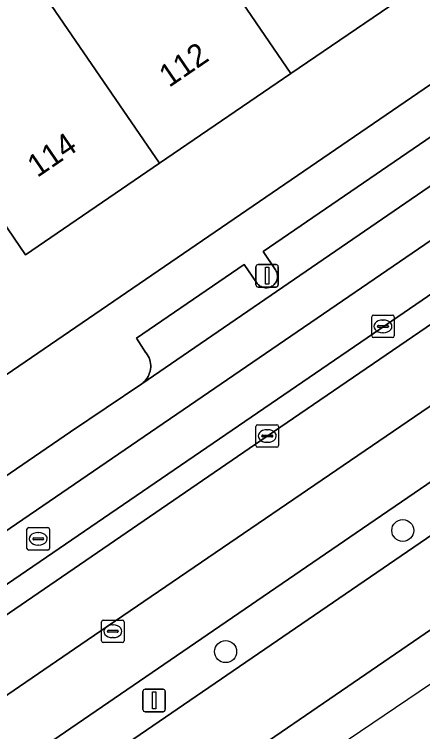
# Model space of a CAD drawing. Extents: x 157445 to 158888, y 383061 to 384688.
# Drawn here: x 158237.61 to 158255.74, y 383403.58 to 383435.44 of the extents above; entities that cross this region are included whole.
import ezdxf

# ---------------------------------------------------------------- set-up
doc = ezdxf.new("R2010")
doc.units = 0
for name, color, linetype in [('IMGEO_Berm_groen', 7, 'Continuous'), ('IMGEO_Boom', 7, 'Continuous'), ('IMGEO_Erf', 7, 'Continuous'), ('IMGEO_Fietspad_gesloten', 7, 'Continuous'), ('IMGEO_Groenvoorziening', 7, 'Continuous'), ('IMGEO_Haag', 7, 'Continuous'), ('IMGEO_Kolk', 7, 'Continuous'), ('IMGEO_Lichtmast', 7, 'Continuous'), ('IMGEO_OVBaan_gesloten', 7, 'Continuous'), ('IMGEO_Pand', 7, 'Continuous'), ('IMGEO_Pand_nummerreeks', 7, 'Continuous'), ('IMGEO_Parkeervlak_open', 7, 'Continuous'), ('IMGEO_Rijbaan_lokaal_open', 7, 'Continuous'), ('IMGEO_Rijbaan_regionaal_gesloten', 7, 'Continuous'), ('IMGEO_Rioolput', 7, 'Continuous'), ('IMGEO_Voetpad_open', 7, 'Continuous')]:
    doc.layers.add(name, color=color, linetype=linetype)

msp = doc.modelspace()

# ---------------------------------------------------------------- linework, layer by layer
at = {"layer": 'IMGEO_Berm_groen'}
msp.add_lwpolyline([(158221.925, 383388.892), (158288.761, 383434.651), (158292.434, 383437.186), (158297.742, 383440.818), (158298.869, 383441.589), (158297.72, 383443.271), (158292.199, 383439.39), (158253.351, 383412.794), (158220.288, 383390.177), (158147.587, 383340.38), (158131.044, 383329.063), (158130.63, 383328.78), (158121.696, 383323.264), (158114.538, 383319.21), (158116.355, 383316.875), (158118.236, 383318.161), (158122.571, 383321.116), (158122.69, 383320.962), (158147.648, 383338.001)], close=True, dxfattribs=at)
at = {"layer": 'IMGEO_Boom'}
for centre in [(158254.856, 383412.515), (158246.986, 383407.135)]:
    msp.add_circle(centre, 0.489, dxfattribs=at)
at = {"layer": 'IMGEO_Erf'}
for points in [[(158261.53, 383440.776), (158255.722, 383436.805), (158249.888, 383432.816), (158244.054, 383428.827), (158238.106, 383424.761), (158235.228, 383428.972), (158233.281, 383427.642), (158233.14, 383427.545), (158234.427, 383425.663), (158228.484, 383421.6), (158224.793, 383426.999), (158230.737, 383431.063), (158231.048, 383430.609), (158231.188, 383430.705), (158233.137, 383432.038), (158231.98, 383433.73), (158237.925, 383437.797), (158243.757, 383441.787), (158249.591, 383445.778), (158255.366, 383449.729), (158256.523, 383448.037)], [(158223.297, 383422.668), (158227.333, 383416.806), (158227.586, 383416.813), (158227.93, 383416.511), (158228.071, 383416.31), (158228.229, 383416.122), (158228.404, 383415.949), (158228.593, 383415.793), (158228.795, 383415.654), (158229.009, 383415.533), (158229.233, 383415.432), (158229.465, 383415.352), (158229.703, 383415.292), (158229.946, 383415.255), (158230.191, 383415.239), (158230.437, 383415.244), (158230.68, 383415.272), (158230.921, 383415.322), (158231.156, 383415.393), (158231.384, 383415.484), (158231.603, 383415.596), (158231.811, 383415.726), (158231.883, 383415.778), (158272.122, 383443.31)]]:
    msp.add_lwpolyline(points, dxfattribs=at)
at = {"layer": 'IMGEO_Fietspad_gesloten'}
for points in [[(158187.266, 383378.304), (158283.613, 383444.253), (158285.485, 383445.421)], [(158264.364, 383433.502), (158243.266, 383419.033), (158240.107, 383416.893), (158231.018, 383410.676), (158222.662, 383405.033), (158216.122, 383400.492), (158211.209, 383397.104), (158189.236, 383382.055), (158186.221, 383380.023), (158186.115, 383379.952), (158185.306, 383379.446), (158177.375, 383375.018), (158176.619, 383374.65), (158176.474, 383374.585), (158172.535, 383372.428), (158169.599, 383370.501), (158169.322, 383370.3), (158168.758, 383369.891), (158163.249, 383365.637), (158161.075, 383363.872), (158159.242, 383362.325), (158158.671, 383361.835)]]:
    msp.add_lwpolyline(points, dxfattribs=at)
at = {"layer": 'IMGEO_Groenvoorziening'}
for points in [[(158248.84, 383416.701), (158278.53, 383437.014), (158282.685, 383439.867), (158290.446, 383445.197), (158291.741, 383446.132), (158293.116, 383447.183)], [(158267.42, 383430.778), (158253.835, 383421.451), (158233.587, 383407.607), (158220.735, 383398.828), (158218.073, 383397), (158207.964, 383390.082), (158175.757, 383368.034), (158174.147, 383366.948), (158170.828, 383364.667), (158169.555, 383363.8), (158154.269, 383353.34), (158144.169, 383346.438), (158136.533, 383341.212)], [(158097.631, 383314.81), (158104.807, 383319.769), (158115.926, 383327.372), (158122.206, 383331.037), (158124.828, 383332.496), (158130.229, 383335.664), (158132.829, 383337.348), (158135.426, 383339.03), (158135.445, 383339.043), (158145.556, 383345.975), (158161.638, 383357.025), (158178.512, 383368.554), (158196.488, 383380.88), (158218.524, 383395.939), (158231.113, 383404.563), (158248.84, 383416.701)]]:
    msp.add_lwpolyline(points, dxfattribs=at)
at = {"layer": 'IMGEO_Haag'}
for points in [[(158097.631, 383314.81), (158104.807, 383319.769), (158115.926, 383327.372), (158122.206, 383331.037), (158124.828, 383332.496), (158130.229, 383335.664), (158132.829, 383337.348), (158135.426, 383339.03), (158135.445, 383339.043), (158145.556, 383345.975), (158161.638, 383357.025), (158178.512, 383368.554), (158196.488, 383380.88), (158218.524, 383395.939), (158231.113, 383404.563), (158248.84, 383416.701), (158278.53, 383437.014)], [(158267.42, 383430.778), (158253.835, 383421.451), (158233.587, 383407.607), (158220.735, 383398.828), (158218.073, 383397), (158207.964, 383390.082), (158175.757, 383368.034), (158174.147, 383366.948), (158170.828, 383364.667), (158169.555, 383363.8), (158154.269, 383353.34), (158144.169, 383346.438), (158136.533, 383341.212)]]:
    msp.add_lwpolyline(points, dxfattribs=at)
at = {"layer": 'IMGEO_Kolk'}
for p, q in [((158253.474, 383421.155), (158253.474, 383422.007)), ((158253.549, 383422.081), (158254.401, 383422.081)), ((158253.962, 383421.861), (158253.987, 383421.861)), ((158254.475, 383422.007), (158254.475, 383421.155)), ((158253.733, 383421.575), (158253.733, 383421.587)), ((158254.171, 383421.538), (158253.773, 383421.538)), ((158253.776, 383421.624), (158254.174, 383421.624)), ((158254.217, 383421.587), (158254.217, 383421.575)), ((158253.985, 383421.301), (158253.96, 383421.301)), ((158254.401, 383421.081), (158253.549, 383421.081)), ((158248.336, 383416.285), (158248.336, 383417.137)), ((158248.411, 383417.211), (158249.263, 383417.211)), ((158249.337, 383417.137), (158249.337, 383416.285)), ((158248.638, 383416.754), (158249.036, 383416.754)), ((158248.824, 383416.991), (158248.849, 383416.991)), ((158248.595, 383416.705), (158248.595, 383416.717)), ((158249.033, 383416.668), (158248.635, 383416.668)), ((158249.079, 383416.717), (158249.079, 383416.705)), ((158249.263, 383416.211), (158248.411, 383416.211)), ((158248.847, 383416.431), (158248.822, 383416.431))]:
    msp.add_line(p, q, dxfattribs=at)
for points in [[(158253.474, 383421.155), (158253.474, 383422.007)], [(158253.549, 383422.081), (158254.401, 383422.081)], [(158254.475, 383422.007), (158254.475, 383421.155)], [(158254.401, 383421.081), (158253.549, 383421.081)], [(158248.336, 383416.285), (158248.336, 383417.137)], [(158248.411, 383417.211), (158249.263, 383417.211)], [(158249.337, 383417.137), (158249.337, 383416.285)], [(158249.263, 383416.211), (158248.411, 383416.211)]]:
    msp.add_lwpolyline(points, dxfattribs=at)
for centre, radius, start, end in [((158253.551, 383422.005), 0.0765, 91.552, 178.448), ((158253.551, 383422.005), 0.0765, 91.552, 178.448), ((158254.399, 383422.005), 0.0765, 1.552, 88.448), ((158254.399, 383422.005), 0.0765, 1.552, 88.448), ((158253.773, 383421.584), 0.0403, 85.8775, 175.7526), ((158253.77, 383421.574), 0.0366, 178.938, 274.7102), ((158254.174, 383421.581), 0.043, 264.8664, 352.4533), ((158254.178, 383421.586), 0.0386, 1.7309, 96.639), ((158253.551, 383421.157), 0.0765, 181.552, 268.448), ((158253.551, 383421.157), 0.0765, 181.552, 268.448), ((158254.399, 383421.157), 0.0765, 271.552, 358.448), ((158254.399, 383421.157), 0.0765, 271.552, 358.448), ((158248.413, 383417.135), 0.0765, 91.552, 178.448), ((158248.413, 383417.135), 0.0765, 91.552, 178.448), ((158249.261, 383417.135), 0.0765, 1.552, 88.448), ((158249.261, 383417.135), 0.0765, 1.552, 88.448), ((158248.635, 383416.714), 0.0403, 85.8775, 175.7526), ((158249.04, 383416.716), 0.0386, 1.7309, 96.639), ((158248.632, 383416.704), 0.0366, 178.938, 274.7102), ((158249.036, 383416.711), 0.043, 264.8664, 352.4533), ((158248.413, 383416.287), 0.0765, 181.552, 268.448), ((158248.413, 383416.287), 0.0765, 181.552, 268.448), ((158249.261, 383416.287), 0.0765, 271.552, 358.448), ((158249.261, 383416.287), 0.0765, 271.552, 358.448)]:
    msp.add_arc(centre, radius, start, end, dxfattribs=at)
for centre, major_axis, ratio, start_param, end_param in [((158253.961, 383421.581), (-0.387, 0.002), 0.722429, 4.712389, 7.853982), ((158253.986, 383421.581), (-0.39, 0.002), 0.717154, 1.570796, 4.712389), ((158248.823, 383416.711), (-0.387, 0.002), 0.722429, 4.712389, 7.853982), ((158248.848, 383416.711), (-0.39, 0.002), 0.717154, 1.570796, 4.712389)]:
    msp.add_ellipse(centre, major_axis=major_axis, ratio=ratio, start_param=start_param, end_param=end_param, dxfattribs=at)
at = {"layer": 'IMGEO_Lichtmast'}
for p, q in [((158248.337, 383423.43), (158248.337, 383424.23)), ((158248.337, 383424.23), (158248.337, 383423.43)), ((158248.437, 383424.33), (158249.227, 383424.33)), ((158249.227, 383424.33), (158248.437, 383424.33)), ((158249.327, 383424.23), (158249.327, 383423.43)), ((158249.327, 383423.43), (158249.327, 383424.23)), ((158249.227, 383423.33), (158248.437, 383423.33)), ((158248.437, 383423.33), (158249.227, 383423.33)), ((158243.318, 383404.566), (158243.318, 383405.366)), ((158243.318, 383405.366), (158243.318, 383404.566)), ((158243.418, 383405.466), (158244.208, 383405.466)), ((158244.208, 383405.466), (158243.418, 383405.466)), ((158244.308, 383405.366), (158244.308, 383404.566)), ((158244.308, 383404.566), (158244.308, 383405.366)), ((158244.208, 383404.466), (158243.418, 383404.466)), ((158243.418, 383404.466), (158244.208, 383404.466))]:
    msp.add_line(p, q, dxfattribs=at)
for points in [[(158248.757, 383424.205), (158248.907, 383424.205), (158248.907, 383423.455), (158248.757, 383423.455), (158248.757, 383424.205)], [(158243.738, 383405.341), (158243.888, 383405.341), (158243.888, 383404.591), (158243.738, 383404.591), (158243.738, 383405.341)]]:
    msp.add_lwpolyline(points, dxfattribs=at)
for centre, start, end in [((158248.437, 383424.23), 90, 180), ((158248.437, 383424.23), 90, 180), ((158249.227, 383424.23), 0, 90), ((158249.227, 383424.23), 360, 90), ((158248.437, 383423.43), 180, 270), ((158248.437, 383423.43), 180, 270), ((158249.227, 383423.43), 270, 0), ((158249.227, 383423.43), 270, 0), ((158243.418, 383405.366), 90, 180), ((158243.418, 383405.366), 90, 180), ((158244.208, 383405.366), 0, 90), ((158244.208, 383405.366), 360, 90), ((158243.418, 383404.566), 180, 270), ((158243.418, 383404.566), 180, 270), ((158244.208, 383404.566), 270, 0), ((158244.208, 383404.566), 270, 0)]:
    msp.add_arc(centre, 0.1, start, end, dxfattribs=at)
at = {"layer": 'IMGEO_OVBaan_gesloten'}
msp.add_lwpolyline([(158105.383, 383303.781), (158135.353, 383324.049), (158142.057, 383328.583), (158290.829, 383429.195), (158320.176, 383449.816), (158338.196, 383462.478), (158337.159, 383463.965), (158306.253, 383442.35), (158269.724, 383417.452), (158230.256, 383390.412), (158196.708, 383367.445), (158164.294, 383345.275), (158134.65, 383324.869), (158121.592, 383315.968), (158104.891, 383304.477)], close=True, dxfattribs=at)
msp.add_lwpolyline([(158288.761, 383434.651), (158221.925, 383388.892), (158147.648, 383338.001), (158122.69, 383320.962), (158122.571, 383321.116), (158118.236, 383318.161), (158116.355, 383316.875), (158107.899, 383311.095), (158102.711, 383307.543), (158104.822, 383304.574), (158104.891, 383304.477), (158121.592, 383315.968), (158134.65, 383324.869), (158164.294, 383345.275), (158196.708, 383367.445), (158230.256, 383390.412), (158269.724, 383417.452)], dxfattribs=at)
at = {"layer": 'IMGEO_Pand'}
for points in [[(158249.888, 383432.816), (158255.722, 383436.805), (158249.703, 383445.615), (158249.591, 383445.778), (158243.757, 383441.787), (158243.86, 383441.637)], [(158237.925, 383437.797), (158238.019, 383437.659), (158244.054, 383428.827), (158249.888, 383432.816), (158243.86, 383441.637), (158243.757, 383441.787)], [(158233.281, 383427.642), (158235.228, 383428.972), (158238.106, 383424.761), (158244.054, 383428.827), (158238.019, 383437.659), (158237.925, 383437.797), (158231.98, 383433.73), (158233.137, 383432.038), (158231.188, 383430.705)]]:
    msp.add_lwpolyline(points, close=True, dxfattribs=at)
at = {"layer": 'IMGEO_Parkeervlak_open'}
msp.add_lwpolyline([(158262.546, 383434.413), (158248.649, 383424.903), (158249.197, 383424.096), (158249.214, 383424.07), (158249.237, 383424.031), (158249.255, 383423.99), (158249.271, 383423.948), (158249.282, 383423.904), (158249.289, 383423.86), (158249.292, 383423.815), (158249.291, 383423.77), (158249.287, 383423.725), (158249.278, 383423.68), (158249.265, 383423.637), (158249.248, 383423.595), (158249.228, 383423.555), (158249.205, 383423.517), (158249.177, 383423.481), (158249.147, 383423.447), (158249.114, 383423.416), (158249.079, 383423.389), (158249.041, 383423.365), (158249.001, 383423.344), (158248.959, 383423.327), (158248.916, 383423.313), (158248.872, 383423.304), (158248.827, 383423.298), (158248.782, 383423.297), (158248.737, 383423.299), (158248.692, 383423.306), (158248.649, 383423.317), (158248.606, 383423.331), (158248.565, 383423.349), (158248.525, 383423.371), (158248.488, 383423.396), (158248.453, 383423.425), (158248.421, 383423.456), (158248.391, 383423.49), (158248.365, 383423.527), (158247.809, 383424.329), (158243.024, 383421.058), (158243.448, 383420.412), (158243.455, 383420.403), (158243.505, 383420.333), (158243.549, 383420.259), (158243.586, 383420.182), (158243.616, 383420.101), (158243.638, 383420.019), (158243.653, 383419.934), (158243.66, 383419.849), (158243.66, 383419.763), (158243.652, 383419.678), (158243.637, 383419.593), (158243.614, 383419.511), (158243.583, 383419.43), (158243.546, 383419.353), (158243.502, 383419.28), (158243.452, 383419.21), (158243.395, 383419.146), (158243.333, 383419.086), (158243.266, 383419.033), (158264.364, 383433.502)], dxfattribs=at)
at = {"layer": 'IMGEO_Rijbaan_lokaal_open'}
for points in [[(158283.613, 383444.253), (158187.266, 383378.304)], [(158233.587, 383407.607), (158253.835, 383421.451), (158267.42, 383430.778), (158279.382, 383438.959), (158282.059, 383440.783)]]:
    msp.add_lwpolyline(points, dxfattribs=at)
at = {"layer": 'IMGEO_Rijbaan_regionaal_gesloten'}
for points in [[(158147.587, 383340.38), (158220.288, 383390.177), (158253.351, 383412.794), (158292.199, 383439.39)], [(158278.53, 383437.014), (158248.84, 383416.701), (158231.113, 383404.563), (158218.524, 383395.939), (158196.488, 383380.88), (158178.512, 383368.554), (158161.638, 383357.025), (158145.556, 383345.975), (158135.445, 383339.043)], [(158138.48, 383337.556), (158158.157, 383351.03), (158164.879, 383355.633), (158168.626, 383358.198), (158174.157, 383361.985), (158187.898, 383371.394), (158211.135, 383387.305), (158217.716, 383391.811), (158240.844, 383407.647), (158257.282, 383418.872)], [(158257.282, 383418.872), (158240.844, 383407.647), (158217.716, 383391.811), (158211.135, 383387.305), (158187.898, 383371.394), (158174.157, 383361.985), (158168.626, 383358.198), (158164.879, 383355.633), (158158.157, 383351.03), (158138.48, 383337.556)]]:
    msp.add_lwpolyline(points, dxfattribs=at)
at = {"layer": 'IMGEO_Rioolput'}
for p, q in [((158238.242, 383412.645), (158239.094, 383412.645)), ((158238.167, 383411.719), (158238.167, 383412.571)), ((158238.655, 383412.425), (158238.68, 383412.425)), ((158239.168, 383412.571), (158239.168, 383411.719)), ((158238.426, 383412.139), (158238.426, 383412.151)), ((158238.864, 383412.102), (158238.466, 383412.102)), ((158238.469, 383412.188), (158238.867, 383412.188)), ((158238.91, 383412.151), (158238.91, 383412.139)), ((158238.678, 383411.865), (158238.653, 383411.865)), ((158239.094, 383411.645), (158238.242, 383411.645)), ((158241.555, 383408.537), (158242.407, 383408.537)), ((158241.48, 383407.611), (158241.48, 383408.463)), ((158241.968, 383408.317), (158241.993, 383408.317)), ((158242.481, 383408.463), (158242.481, 383407.611)), ((158241.739, 383408.031), (158241.739, 383408.043)), ((158242.177, 383407.994), (158241.779, 383407.994)), ((158241.782, 383408.08), (158242.18, 383408.08)), ((158242.223, 383408.043), (158242.223, 383408.031)), ((158242.407, 383407.537), (158241.555, 383407.537)), ((158241.991, 383407.757), (158241.966, 383407.757))]:
    msp.add_line(p, q, dxfattribs=at)
for points in [[(158238.242, 383412.645), (158239.094, 383412.645)], [(158238.167, 383411.719), (158238.167, 383412.571)], [(158239.168, 383412.571), (158239.168, 383411.719)], [(158239.094, 383411.645), (158238.242, 383411.645)], [(158241.555, 383408.537), (158242.407, 383408.537)], [(158241.48, 383407.611), (158241.48, 383408.463)], [(158242.481, 383408.463), (158242.481, 383407.611)], [(158242.407, 383407.537), (158241.555, 383407.537)]]:
    msp.add_lwpolyline(points, dxfattribs=at)
for centre, radius, start, end in [((158238.244, 383412.569), 0.0765, 91.552, 178.448), ((158238.244, 383412.569), 0.0765, 91.552, 178.448), ((158239.092, 383412.569), 0.0765, 1.552, 88.448), ((158239.092, 383412.569), 0.0765, 1.552, 88.448), ((158238.466, 383412.148), 0.0403, 85.8775, 175.7526), ((158238.463, 383412.138), 0.0366, 178.938, 274.7102), ((158238.867, 383412.145), 0.043, 264.8664, 352.4533), ((158238.871, 383412.15), 0.0386, 1.7309, 96.639), ((158238.244, 383411.721), 0.0765, 181.552, 268.448), ((158238.244, 383411.721), 0.0765, 181.552, 268.448), ((158239.092, 383411.721), 0.0765, 271.552, 358.448), ((158239.092, 383411.721), 0.0765, 271.552, 358.448), ((158241.557, 383408.461), 0.0765, 91.552, 178.448), ((158241.557, 383408.461), 0.0765, 91.552, 178.448), ((158242.405, 383408.461), 0.0765, 1.552, 88.448), ((158242.405, 383408.461), 0.0765, 1.552, 88.448), ((158241.779, 383408.04), 0.0403, 85.8775, 175.7526), ((158241.776, 383408.03), 0.0366, 178.938, 274.7102), ((158242.18, 383408.037), 0.043, 264.8664, 352.4533), ((158242.184, 383408.042), 0.0386, 1.7309, 96.639), ((158241.557, 383407.613), 0.0765, 181.552, 268.448), ((158241.557, 383407.613), 0.0765, 181.552, 268.448), ((158242.405, 383407.613), 0.0765, 271.552, 358.448), ((158242.405, 383407.613), 0.0765, 271.552, 358.448)]:
    msp.add_arc(centre, radius, start, end, dxfattribs=at)
for centre, major_axis, ratio, start_param, end_param in [((158238.654, 383412.145), (-0.387, 0.002), 0.722429, 4.712389, 7.853982), ((158238.679, 383412.145), (-0.39, 0.002), 0.717154, 1.570796, 4.712389), ((158241.967, 383408.037), (-0.387, 0.002), 0.722429, 4.712389, 7.853982), ((158241.992, 383408.037), (-0.39, 0.002), 0.717154, 1.570796, 4.712389)]:
    msp.add_ellipse(centre, major_axis=major_axis, ratio=ratio, start_param=start_param, end_param=end_param, dxfattribs=at)
at = {"layer": 'IMGEO_Voetpad_open'}
for points in [[(158272.122, 383443.31), (158231.883, 383415.778), (158231.811, 383415.726), (158231.603, 383415.596), (158225.956, 383411.829), (158222.607, 383409.496)], [(158231.018, 383410.676), (158240.107, 383416.893), (158243.266, 383419.033), (158243.333, 383419.086), (158243.395, 383419.146), (158243.452, 383419.21), (158243.502, 383419.28), (158243.546, 383419.353), (158243.583, 383419.43), (158243.614, 383419.511), (158243.637, 383419.593), (158243.652, 383419.678), (158243.66, 383419.763), (158243.66, 383419.849), (158243.653, 383419.934), (158243.638, 383420.019), (158243.616, 383420.101), (158243.586, 383420.182), (158243.549, 383420.259), (158243.505, 383420.333), (158243.455, 383420.403), (158243.448, 383420.412), (158243.024, 383421.058), (158247.809, 383424.329), (158248.365, 383423.527), (158248.391, 383423.49), (158248.421, 383423.456), (158248.453, 383423.425), (158248.488, 383423.396), (158248.525, 383423.371), (158248.565, 383423.349), (158248.606, 383423.331), (158248.649, 383423.317), (158248.692, 383423.306), (158248.737, 383423.299), (158248.782, 383423.297), (158248.827, 383423.298), (158248.872, 383423.304), (158248.916, 383423.313), (158248.959, 383423.327), (158249.001, 383423.344), (158249.041, 383423.365), (158249.079, 383423.389), (158249.114, 383423.416), (158249.147, 383423.447), (158249.177, 383423.481), (158249.205, 383423.517), (158249.228, 383423.555), (158249.248, 383423.595), (158249.265, 383423.637), (158249.278, 383423.68), (158249.287, 383423.725), (158249.291, 383423.77), (158249.292, 383423.815), (158249.289, 383423.86), (158249.282, 383423.904), (158249.271, 383423.948), (158249.255, 383423.99), (158249.237, 383424.031), (158249.214, 383424.07), (158249.197, 383424.096), (158248.649, 383424.903), (158262.546, 383434.413)]]:
    msp.add_lwpolyline(points, dxfattribs=at)

# ---------------------------------------------------------------- texts
at = {"layer": 'IMGEO_Pand_nummerreeks'}
for s, p in [('112', (158244.477, 383432.17)), ('114', (158238.625, 383428.168))]:
    msp.add_text(s, height=1, rotation=34.3604, dxfattribs=at).set_placement(p)

doc.saveas('drawing.dxf')
